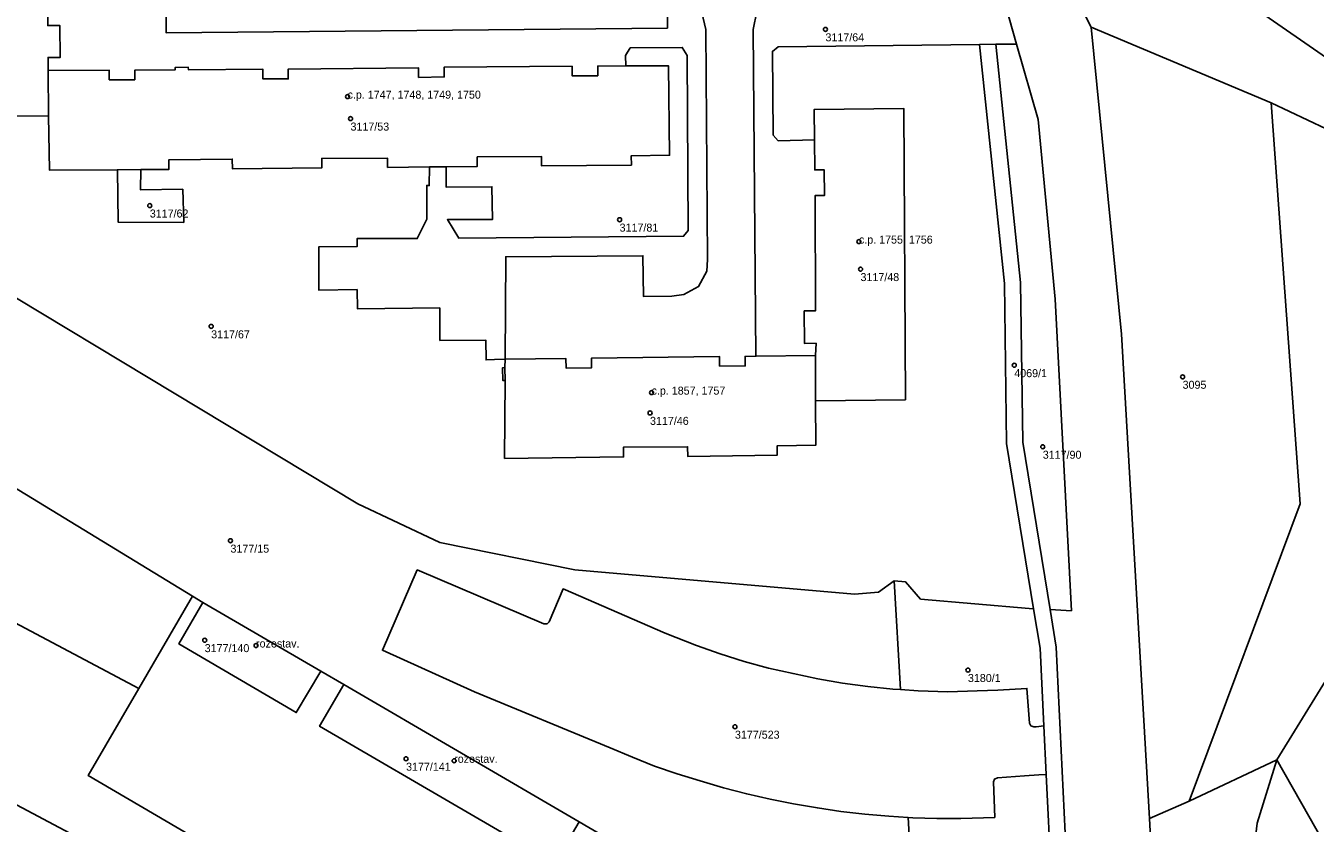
# Model space of a CAD drawing. Extents: x -878211 to -870363, y -1058464 to -1052522.
# Drawn here: x -874028.3 to -873867.2, y -1056949.6 to -1056850 of the extents above; entities that cross this region are included whole.
import ezdxf

# ---------------------------------------------------------------- set-up
doc = ezdxf.new("R2010")
doc.units = 0
for name, color, linetype in [('Vrstva 50', 7, 'Continuous'), ('Vrstva 51', 7, 'Continuous'), ('Vrstva 52', 7, 'Continuous')]:
    doc.layers.add(name, color=color, linetype=linetype)

msp = doc.modelspace()

# ---------------------------------------------------------------- linework, layer by layer
at = {"layer": 'Vrstva 50'}
for centre in [(-873928.43, -1056850.41994), (-873988.14, -1056858.81994), (-873987.77, -1056861.56994), (-874012.85, -1056872.42994), (-873954.15, -1056874.18994), (-873924.25, -1056876.92994), (-873924.05, -1056880.36994), (-874005.18, -1056887.51994), (-873904.84, -1056892.36994), (-873883.81, -1056893.81994), (-873950.16, -1056895.78994), (-873950.35, -1056898.32994), (-873901.28, -1056902.55994), (-874002.77, -1056914.28994), (-874005.99, -1056926.71994), (-873999.57, -1056927.37994), (-873910.63, -1056930.44994), (-873939.74, -1056937.52994), (-873980.83, -1056941.52994), (-873974.82, -1056941.77994)]:
    msp.add_circle(centre, 0.25, dxfattribs=at)
at = {"layer": 'Vrstva 51'}
for points in [[(-873604.63, -1056840.36), (-873616.81, -1056858.72), (-873698.72, -1056860.89), (-873766.2, -1056862.68), (-873840.53, -1056864.49), (-873842.61, -1056864.54), (-873904.62, -1056821.65), (-873906.75, -1056817.03), (-873920.07, -1056788.11), (-873936.35, -1056752.76), (-873946.72, -1056739.16), (-873949.55, -1056741.32), (-873950.29, -1056741.89), (-873940.24, -1056755.07), (-873908.21, -1056824.62), (-873843.96, -1056869.08), (-873693.74, -1056865.21), (-873616.51, -1056863.22), (-873608.69, -1056855.43), (-873599.24, -1056841.86)], [(-874049.34, -1056914.15), (-874014.23, -1056932.75), (-874007.51, -1056921.23), (-874042.84, -1056899.69), (-874076.67, -1056880.17), (-874135.18, -1056846.79), (-874225.05, -1056794.29), (-874220.11, -1056799.06), (-874203.06, -1056813.57), (-874129.69, -1056863.48), (-874108.33, -1056874.46), (-874102.53, -1056878.64), (-874078.93, -1056895.35), (-874073.45, -1056899.05), (-874056.93, -1056909.47)], [(-874038.33, -1056836.04), (-874036.85, -1056836.02), (-874036.75, -1056861.29), (-874025.49, -1056861.21), (-874025.55, -1056855.56), (-874025.56, -1056853.92), (-874024.03, -1056853.91), (-874024.08, -1056849.94), (-874025.59, -1056849.95), (-874025.75, -1056836.37), (-874025.88, -1056824.74), (-874037.05, -1056824.85), (-874036.93, -1056830.52), (-874036.91, -1056831.66), (-874036.9, -1056832), (-874038.38, -1056832.02), (-874038.34, -1056835.71)], [(-873872.76, -1056859.6), (-873856.69, -1056867.17), (-873849.21, -1056874.21), (-873847.06, -1056896.27), (-873844.64, -1056897.18), (-873805.03, -1056873.43), (-873843.96, -1056869.08), (-873908.21, -1056824.62), (-873895.24, -1056850.14)], [(-873891.46, -1056888.5), (-873887.93, -1056948.97), (-873882.99, -1056946.82), (-873869.1, -1056909.7), (-873872.76, -1056859.6), (-873895.24, -1056850.14)], [(-873975.82, -1056867.58), (-873975.8, -1056870.14), (-873970.1, -1056870.08), (-873970.01, -1056874.16), (-873975.66, -1056874.17), (-873974.22, -1056876.5), (-873946.15, -1056876.25), (-873945.59, -1056875.55), (-873945.69, -1056853.68), (-873946.33, -1056852.68), (-873952.81, -1056852.74), (-873953.42, -1056853.7), (-873953.37, -1056854.98), (-873948.06, -1056854.96), (-873947.91, -1056866.14), (-873952.69, -1056866.2), (-873952.67, -1056867.36), (-873963.9, -1056867.47), (-873963.92, -1056866.29), (-873971.94, -1056866.35), (-873971.93, -1056867.53)], [(-873900.85, -1056943.5), (-873900.25, -1056956.07), (-873898.25, -1056955.98), (-873899.61, -1056927.59), (-873900.37, -1056922.89), (-873903.77, -1056901.98), (-873904.06, -1056882.04), (-873907.15, -1056852.28), (-873909.17, -1056852.29), (-873906.07, -1056882.18), (-873905.81, -1056902.14), (-873902.42, -1056922.78), (-873901.61, -1056927.7), (-873901.14, -1056937.42)], [(-873903.77, -1056901.98), (-873900.37, -1056922.89), (-873897.7, -1056923.04), (-873899.71, -1056884.1), (-873901.85, -1056861.67), (-873904.55, -1056852.25), (-873907.15, -1056852.28), (-873904.06, -1056882.04)], [(-874025.55, -1056855.56), (-874025.49, -1056861.21), (-874025.37, -1056868.01), (-874016.89, -1056867.96), (-874013.95, -1056867.94), (-874010.46, -1056867.92), (-874010.47, -1056866.72), (-874002.54, -1056866.62), (-874002.53, -1056867.82), (-873991.36, -1056867.73), (-873991.37, -1056866.53), (-873983.16, -1056866.49), (-873983.14, -1056867.66), (-873977.91, -1056867.6), (-873975.82, -1056867.58), (-873971.93, -1056867.53), (-873971.94, -1056866.35), (-873963.92, -1056866.29), (-873963.9, -1056867.47), (-873952.67, -1056867.36), (-873952.69, -1056866.2), (-873947.91, -1056866.14), (-873948.06, -1056854.96), (-873953.37, -1056854.98), (-873956.88, -1056855), (-873956.88, -1056856.21), (-873960.09, -1056856.22), (-873960.09, -1056855.02), (-873976.08, -1056855.15), (-873976.05, -1056856.36), (-873979.27, -1056856.42), (-873979.29, -1056855.21), (-873995.54, -1056855.38), (-873995.55, -1056856.61), (-873998.74, -1056856.58), (-873998.73, -1056855.38), (-874008.03, -1056855.46), (-874008.05, -1056855.14), (-874009.67, -1056855.16), (-874009.66, -1056855.47), (-874014.73, -1056855.52), (-874014.73, -1056856.72), (-874017.91, -1056856.72), (-874017.92, -1056855.53)], [(-873856.69, -1056867.17), (-873872.76, -1056859.6), (-873869.1, -1056909.7), (-873882.99, -1056946.82), (-873872.02, -1056941.65), (-873844.64, -1056897.18), (-873847.06, -1056896.27), (-873849.21, -1056874.21)], [(-873929.84, -1056860.41), (-873929.8, -1056864.2), (-873929.76, -1056867.98), (-873928.58, -1056867.97), (-873928.55, -1056871.17), (-873929.73, -1056871.18), (-873929.66, -1056885.57), (-873931.08, -1056885.58), (-873931.05, -1056889.65), (-873929.61, -1056889.63), (-873929.67, -1056891.15), (-873929.68, -1056896.81), (-873918.43, -1056896.69), (-873918.65, -1056860.29)], [(-874129.69, -1056863.48), (-874140.36, -1056880.4), (-874060.01, -1056931.07), (-874021.49, -1056951.53), (-873984.94, -1056965.93), (-873981.56, -1056966.45), (-874020.56, -1056943.6), (-874014.23, -1056932.75), (-874049.34, -1056914.15), (-874056.93, -1056909.47), (-874073.45, -1056899.05), (-874078.93, -1056895.35), (-874102.53, -1056878.64), (-874108.33, -1056874.46)], [(-874013.95, -1056867.94), (-874016.89, -1056867.96), (-874016.8, -1056874.48), (-874008.61, -1056874.52), (-874008.73, -1056870.39), (-874014.02, -1056870.46)], [(-873844.64, -1056897.18), (-873872.02, -1056941.65), (-873797.84, -1057072.28), (-873673.86, -1057000.71), (-873709.07, -1056941.13), (-873712.1, -1056942.73), (-873755.06, -1056869.97), (-873805.03, -1056873.43)], [(-873960.84, -1056892.72), (-873960.86, -1056891.53), (-873968.46, -1056891.62), (-873968.47, -1056892.67), (-873968.76, -1056892.68), (-873968.73, -1056894.28), (-873968.45, -1056894.28), (-873968.51, -1056904), (-873953.66, -1056903.82), (-873953.67, -1056902.62), (-873945.66, -1056902.55), (-873945.64, -1056903.75), (-873934.45, -1056903.6), (-873934.46, -1056902.42), (-873929.65, -1056902.36), (-873929.68, -1056896.81), (-873929.67, -1056891.15), (-873937.11, -1056891.24), (-873938.48, -1056891.26), (-873938.46, -1056892.45), (-873941.65, -1056892.48), (-873941.66, -1056891.29), (-873957.68, -1056891.49), (-873957.66, -1056892.69)], [(-873907.3, -1056944.06), (-873906.95, -1056943.9), (-873903.58, -1056943.66), (-873901.78, -1056943.52), (-873900.85, -1056943.5), (-873901.14, -1056937.42), (-873902.12, -1056937.52), (-873902.4, -1056937.54), (-873902.76, -1056937.4), (-873902.93, -1056937.08), (-873903.26, -1056932.74), (-873906.89, -1056932.94), (-873909.49, -1056933.05), (-873913.13, -1056933.15), (-873916.86, -1056933.05), (-873919.05, -1056932.89), (-873920.02, -1056932.83), (-873923.14, -1056932.5), (-873926.3, -1056932.09), (-873929.38, -1056931.56), (-873932.47, -1056930.89), (-873935.56, -1056930.19), (-873938.57, -1056929.36), (-873941.58, -1056928.4), (-873944.56, -1056927.39), (-873948.45, -1056925.82), (-873961.21, -1056920.3), (-873962.95, -1056924.42), (-873963.19, -1056924.67), (-873963.6, -1056924.67), (-873979.44, -1056917.94), (-873983.79, -1056927.97), (-873972.27, -1056933.16), (-873955.34, -1056940.16), (-873952.55, -1056941.33), (-873949.77, -1056942.43), (-873946.94, -1056943.41), (-873944.08, -1056944.3), (-873941.18, -1056945.15), (-873938.26, -1056945.91), (-873935.35, -1056946.57), (-873932.41, -1056947.15), (-873929.44, -1056947.66), (-873926.49, -1056948.1), (-873923.51, -1056948.45), (-873920.51, -1056948.71), (-873918.11, -1056948.85), (-873917.52, -1056948.89), (-873914.5, -1056948.99), (-873911.5, -1056949), (-873907.28, -1056948.86), (-873907.42, -1056944.41)], [(-873903.26, -1056932.74), (-873902.93, -1056937.08), (-873902.76, -1056937.4), (-873902.4, -1056937.54), (-873902.12, -1056937.52), (-873901.14, -1056937.42), (-873901.61, -1056927.7), (-873902.42, -1056922.78), (-873902.99, -1056922.75), (-873916.54, -1056921.58), (-873918.41, -1056919.44), (-873919.86, -1056919.3), (-873919.05, -1056932.89), (-873916.86, -1056933.05), (-873913.13, -1056933.15), (-873909.49, -1056933.05), (-873906.89, -1056932.94)], [(-874006.21, -1056921.99), (-874009.2, -1056927.18), (-873994.54, -1056935.75), (-873991.46, -1056930.6)], [(-873988.6, -1056932.27), (-873991.63, -1056937.46), (-873972.19, -1056948.79), (-873962.24, -1056954.58), (-873959.22, -1056949.41)], [(-873856.51, -1057143.18), (-873856, -1057126.59), (-873855.59, -1057113.18), (-873859.53, -1057099.33), (-873861.95, -1057049.13), (-873875.62, -1056959.25), (-873874.5, -1056949.59), (-873872.02, -1056941.65), (-873882.99, -1056946.82), (-873887.93, -1056948.97), (-873887.66, -1056954.58), (-873884.35, -1057010.32), (-873881.61, -1057032.55)], [(-873918.11, -1056948.85), (-873917.62, -1056957.07), (-873910.53, -1056956.56), (-873900.25, -1056956.07), (-873900.85, -1056943.5), (-873901.78, -1056943.52), (-873903.58, -1056943.66), (-873906.95, -1056943.9), (-873907.3, -1056944.06), (-873907.42, -1056944.41), (-873907.28, -1056948.86), (-873911.5, -1056949), (-873914.5, -1056948.99), (-873917.52, -1056948.89)]]:
    msp.add_lwpolyline(points, close=True, dxfattribs=at)
for points in [[(-874156.66, -1056907.49), (-874136.75, -1056919.68), (-874118.33, -1056927.78), (-874098.29, -1056936.6), (-874078.24, -1056945.42), (-874058.2, -1056954.24), (-874038.15, -1056963.06), (-874037.51, -1056961.6), (-874024.26, -1056967.4), (-874010.99, -1056973.2), (-873996.88, -1056979.37), (-873982.81, -1056985.53), (-873969.85, -1056991.2), (-873968.72, -1056991.43), (-873957.55, -1056993.69), (-873942.44, -1056994.26), (-873933.49, -1056994.6), (-873981.56, -1056966.45), (-873984.94, -1056965.93), (-874021.49, -1056951.53), (-874060.01, -1056931.07), (-874140.36, -1056880.4), (-874129.69, -1056863.48), (-874203.06, -1056813.57)], [(-873856.51, -1057143.18), (-873881.61, -1057032.55), (-873884.35, -1057010.32), (-873887.66, -1056954.58), (-873887.93, -1056948.97), (-873891.46, -1056888.5), (-873895.24, -1056850.14), (-873908.21, -1056824.62)], [(-873948.19, -1056845.24), (-873948.18, -1056850.25), (-874010.8, -1056850.85), (-874010.84, -1056845.75)], [(-874010.84, -1056845.75), (-874010.8, -1056850.85), (-873948.18, -1056850.25), (-873948.19, -1056845.24)], [(-874024.08, -1056849.94), (-874024.03, -1056853.91), (-874025.56, -1056853.92), (-874025.55, -1056855.56), (-874017.92, -1056855.53), (-874017.91, -1056856.72), (-874014.73, -1056856.72), (-874014.73, -1056855.52), (-874009.66, -1056855.47), (-874009.67, -1056855.16), (-874008.05, -1056855.14), (-874008.03, -1056855.46), (-873998.73, -1056855.38), (-873998.74, -1056856.58), (-873995.55, -1056856.61), (-873995.54, -1056855.38), (-873979.29, -1056855.21), (-873979.27, -1056856.42), (-873976.05, -1056856.36), (-873976.08, -1056855.15), (-873960.09, -1056855.02), (-873960.09, -1056856.22), (-873956.88, -1056856.21), (-873956.88, -1056855), (-873953.37, -1056854.98), (-873953.42, -1056853.7), (-873952.81, -1056852.74), (-873946.33, -1056852.68), (-873945.69, -1056853.68), (-873945.59, -1056875.55), (-873946.15, -1056876.25), (-873974.22, -1056876.5), (-873975.66, -1056874.17), (-873970.01, -1056874.16), (-873970.1, -1056870.08), (-873975.8, -1056870.14), (-873975.82, -1056867.58), (-873977.91, -1056867.6), (-873977.93, -1056869.93), (-873978.24, -1056869.9), (-873978.22, -1056874.14), (-873979.44, -1056876.54), (-873986.92, -1056876.52), (-873986.92, -1056877.52), (-873991.72, -1056877.56), (-873991.71, -1056883.01), (-873986.94, -1056882.91), (-873986.9, -1056885.31), (-873976.62, -1056885.22), (-873976.6, -1056889.28), (-873970.85, -1056889.24), (-873970.84, -1056891.71), (-873969.76, -1056891.67), (-873968.46, -1056891.62), (-873968.38, -1056878.82), (-873951.24, -1056878.7), (-873951.18, -1056883.78), (-873947.61, -1056883.75), (-873946.11, -1056883.52), (-873944.29, -1056882.55), (-873943.26, -1056880.64), (-873943.18, -1056879.16), (-873943.39, -1056850.43), (-873943.87, -1056848.32)], [(-873943.87, -1056848.32), (-873943.39, -1056850.43), (-873943.18, -1056879.16), (-873943.26, -1056880.64), (-873944.29, -1056882.55), (-873946.11, -1056883.52), (-873947.61, -1056883.75), (-873951.18, -1056883.78), (-873951.24, -1056878.7), (-873968.38, -1056878.82), (-873968.46, -1056891.62), (-873960.86, -1056891.53), (-873960.84, -1056892.72), (-873957.66, -1056892.69), (-873957.68, -1056891.49), (-873941.66, -1056891.29), (-873941.65, -1056892.48), (-873938.46, -1056892.45), (-873938.48, -1056891.26), (-873937.11, -1056891.24), (-873937.46, -1056850.42), (-873936.99, -1056848.2)], [(-873936.99, -1056848.2), (-873937.46, -1056850.42), (-873937.11, -1056891.24), (-873929.67, -1056891.15), (-873929.61, -1056889.63), (-873931.05, -1056889.65), (-873931.08, -1056885.58), (-873929.66, -1056885.57), (-873929.73, -1056871.18), (-873928.55, -1056871.17), (-873928.58, -1056867.97), (-873929.76, -1056867.98), (-873929.8, -1056864.2), (-873934.32, -1056864.34), (-873934.95, -1056863.63), (-873935.06, -1056853.17), (-873934.33, -1056852.58), (-873909.17, -1056852.29), (-873907.15, -1056852.28), (-873904.55, -1056852.25), (-873905.95, -1056847.41)], [(-873905.95, -1056847.41), (-873904.55, -1056852.25), (-873901.85, -1056861.67), (-873899.71, -1056884.1), (-873897.7, -1056923.04), (-873900.37, -1056922.89), (-873899.61, -1056927.59), (-873898.25, -1056955.98), (-873898.03, -1056955.97), (-873897.18, -1056955.92), (-873896.36, -1056973.46), (-873895.72, -1056985.08), (-873893.67, -1057021.77), (-873892.27, -1057033.58), (-873889.52, -1057047.9), (-873887.76, -1057055.87), (-873882.49, -1057079.7), (-873873.31, -1057121.91), (-873867.32, -1057147.86)], [(-874032.81, -1056882.03), (-873986.86, -1056909.69), (-873976.6, -1056914.5), (-873959.75, -1056917.91), (-873924.82, -1056920.96), (-873921.8, -1056920.73), (-873919.86, -1056919.3), (-873918.41, -1056919.44), (-873916.54, -1056921.58), (-873902.99, -1056922.75), (-873902.42, -1056922.78), (-873905.81, -1056902.14), (-873906.07, -1056882.18), (-873909.17, -1056852.29), (-873934.33, -1056852.58), (-873935.06, -1056853.17), (-873934.95, -1056863.63), (-873934.32, -1056864.34), (-873929.8, -1056864.2), (-873929.84, -1056860.41), (-873918.65, -1056860.29), (-873918.43, -1056896.69), (-873929.68, -1056896.81), (-873929.65, -1056902.36), (-873934.46, -1056902.42), (-873934.45, -1056903.6), (-873945.64, -1056903.75), (-873945.66, -1056902.55), (-873953.67, -1056902.62), (-873953.66, -1056903.82), (-873968.51, -1056904), (-873968.45, -1056894.28), (-873968.73, -1056894.28), (-873968.76, -1056892.68), (-873968.47, -1056892.67), (-873968.46, -1056891.62), (-873969.76, -1056891.67), (-873970.84, -1056891.71), (-873970.85, -1056889.24), (-873976.6, -1056889.28), (-873976.62, -1056885.22), (-873986.9, -1056885.31), (-873986.94, -1056882.91), (-873991.71, -1056883.01), (-873991.72, -1056877.56), (-873986.92, -1056877.52), (-873986.92, -1056876.52), (-873979.44, -1056876.54), (-873978.22, -1056874.14), (-873978.24, -1056869.9), (-873977.93, -1056869.93), (-873977.91, -1056867.6), (-873983.14, -1056867.66), (-873983.16, -1056866.49), (-873991.37, -1056866.53), (-873991.36, -1056867.73), (-874002.53, -1056867.82), (-874002.54, -1056866.62), (-874010.47, -1056866.72), (-874010.46, -1056867.92), (-874013.95, -1056867.94), (-874014.02, -1056870.46), (-874008.73, -1056870.39), (-874008.61, -1056874.52), (-874016.8, -1056874.48), (-874016.89, -1056867.96), (-874025.37, -1056868.01), (-874025.49, -1056861.21), (-874036.75, -1056861.29)], [(-873917.62, -1056957.07), (-873918.11, -1056948.85), (-873920.51, -1056948.71), (-873923.51, -1056948.45), (-873926.49, -1056948.1), (-873929.44, -1056947.66), (-873932.41, -1056947.15), (-873935.35, -1056946.57), (-873938.26, -1056945.91), (-873941.18, -1056945.15), (-873944.08, -1056944.3), (-873946.94, -1056943.41), (-873949.77, -1056942.43), (-873952.55, -1056941.33), (-873955.34, -1056940.16), (-873972.27, -1056933.16), (-873983.79, -1056927.97), (-873979.44, -1056917.94), (-873963.6, -1056924.67), (-873963.19, -1056924.67), (-873962.95, -1056924.42), (-873961.21, -1056920.3), (-873948.45, -1056925.82), (-873944.56, -1056927.39), (-873941.58, -1056928.4), (-873938.57, -1056929.36), (-873935.56, -1056930.19), (-873932.47, -1056930.89), (-873929.38, -1056931.56), (-873926.3, -1056932.09), (-873923.14, -1056932.5), (-873920.02, -1056932.83), (-873919.05, -1056932.89), (-873919.86, -1056919.3), (-873921.8, -1056920.73), (-873924.82, -1056920.96), (-873959.75, -1056917.91), (-873976.6, -1056914.5), (-873986.86, -1056909.69), (-874032.81, -1056882.03)], [(-874042.84, -1056899.69), (-874007.51, -1056921.23), (-874006.21, -1056921.99), (-873991.46, -1056930.6), (-873988.6, -1056932.27), (-873959.22, -1056949.41), (-873956.29, -1056951.12)], [(-873571.9, -1057164.95), (-873603.64, -1057115.36), (-873646.95, -1057049.06), (-873663.43, -1057018.39), (-873649.57, -1057009.83), (-873687.72, -1056941.74), (-873643.87, -1056914.15), (-873662.81, -1056904.24), (-873704.72, -1056929.29), (-873709.07, -1056941.13), (-873673.86, -1057000.71), (-873797.84, -1057072.28), (-873872.02, -1056941.65), (-873874.5, -1056949.59), (-873875.62, -1056959.25), (-873861.95, -1057049.13), (-873859.53, -1057099.33), (-873855.59, -1057113.18), (-873856, -1057126.59), (-873787.09, -1057093.26), (-873671.57, -1057028.78), (-873658.46, -1057052.59), (-873628.55, -1057098.75), (-873585.02, -1057169.44)], [(-873956.29, -1056951.12), (-873959.22, -1056949.41), (-873962.24, -1056954.58), (-873972.19, -1056948.79), (-873991.63, -1056937.46), (-873988.6, -1056932.27), (-873991.46, -1056930.6), (-873994.54, -1056935.75), (-874009.2, -1056927.18), (-874006.21, -1056921.99), (-874007.51, -1056921.23), (-874014.23, -1056932.75), (-874020.56, -1056943.6), (-873981.56, -1056966.45)]]:
    msp.add_lwpolyline(points, dxfattribs=at)
at = {"layer": 'Vrstva 52'}
for points in [[(-874025.75, -1056836.37), (-874025.88, -1056824.74), (-874037.05, -1056824.85), (-874036.93, -1056830.52), (-874036.91, -1056831.66), (-874036.9, -1056832), (-874038.38, -1056832.02), (-874038.34, -1056835.71), (-874038.33, -1056836.04), (-874036.85, -1056836.02), (-874036.75, -1056861.29), (-874025.49, -1056861.21), (-874025.55, -1056855.56), (-874025.56, -1056853.92), (-874024.03, -1056853.91), (-874024.08, -1056849.94), (-874025.59, -1056849.95)], [(-874010.47, -1056866.72), (-874002.54, -1056866.62), (-874002.53, -1056867.82), (-873991.36, -1056867.73), (-873991.37, -1056866.53), (-873983.16, -1056866.49), (-873983.14, -1056867.66), (-873977.91, -1056867.6), (-873975.82, -1056867.58), (-873971.93, -1056867.53), (-873971.94, -1056866.35), (-873963.92, -1056866.29), (-873963.9, -1056867.47), (-873952.67, -1056867.36), (-873952.69, -1056866.2), (-873947.91, -1056866.14), (-873948.06, -1056854.96), (-873953.37, -1056854.98), (-873956.88, -1056855), (-873956.88, -1056856.21), (-873960.09, -1056856.22), (-873960.09, -1056855.02), (-873976.08, -1056855.15), (-873976.05, -1056856.36), (-873979.27, -1056856.42), (-873979.29, -1056855.21), (-873995.54, -1056855.38), (-873995.55, -1056856.61), (-873998.74, -1056856.58), (-873998.73, -1056855.38), (-874008.03, -1056855.46), (-874008.05, -1056855.14), (-874009.67, -1056855.16), (-874009.66, -1056855.47), (-874014.73, -1056855.52), (-874014.73, -1056856.72), (-874017.91, -1056856.72), (-874017.92, -1056855.53), (-874025.55, -1056855.56), (-874025.49, -1056861.21), (-874025.37, -1056868.01), (-874016.89, -1056867.96), (-874013.95, -1056867.94), (-874010.46, -1056867.92)], [(-873928.55, -1056871.17), (-873929.73, -1056871.18), (-873929.66, -1056885.57), (-873931.08, -1056885.58), (-873931.05, -1056889.65), (-873929.61, -1056889.63), (-873929.67, -1056891.15), (-873929.68, -1056896.81), (-873918.43, -1056896.69), (-873918.65, -1056860.29), (-873929.84, -1056860.41), (-873929.8, -1056864.2), (-873929.76, -1056867.98), (-873928.58, -1056867.97)], [(-873968.51, -1056904), (-873953.66, -1056903.82), (-873953.67, -1056902.62), (-873945.66, -1056902.55), (-873945.64, -1056903.75), (-873934.45, -1056903.6), (-873934.46, -1056902.42), (-873929.65, -1056902.36), (-873929.68, -1056896.81), (-873929.67, -1056891.15), (-873937.11, -1056891.24), (-873938.48, -1056891.26), (-873938.46, -1056892.45), (-873941.65, -1056892.48), (-873941.66, -1056891.29), (-873957.68, -1056891.49), (-873957.66, -1056892.69), (-873960.84, -1056892.72), (-873960.86, -1056891.53), (-873968.46, -1056891.62), (-873968.47, -1056892.67), (-873968.45, -1056894.28)], [(-874006.21, -1056921.99), (-874009.2, -1056927.18), (-873994.54, -1056935.75), (-873991.46, -1056930.6)], [(-873988.6, -1056932.27), (-873991.63, -1056937.46), (-873972.19, -1056948.79), (-873962.24, -1056954.58), (-873959.22, -1056949.41)]]:
    msp.add_lwpolyline(points, close=True, dxfattribs=at)

# ---------------------------------------------------------------- texts
at = {"layer": 'Vrstva 50'}
for s, p in [('3117/64', (-873928.43, -1056851.909)), ('c.p. 1747, 1748, 1749, 1750', (-873988.14, -1056859.07)), ('3117/53', (-873987.77, -1056863.059)), ('3117/62', (-874012.85, -1056873.919)), ('3117/81', (-873954.15, -1056875.679)), ('c.p. 1755, 1756', (-873924.25, -1056877.179)), ('3117/48', (-873924.05, -1056881.859)), ('3117/67', (-874005.18, -1056889.009)), ('4069/1', (-873904.84, -1056893.859)), ('c.p. 1857, 1757', (-873950.16, -1056896.04)), ('3095', (-873883.81, -1056895.309)), ('3117/46', (-873950.35, -1056899.819)), ('3117/90', (-873901.28, -1056904.049)), ('3177/15', (-874002.77, -1056915.779)), ('3177/140', (-874005.99, -1056928.209)), ('rozestav.', (-873999.57, -1056927.629)), ('3180/1', (-873910.63, -1056931.939)), ('3177/523', (-873939.74, -1056939.019)), ('3177/141', (-873980.83, -1056943.019)), ('rozestav.', (-873974.82, -1056942.03))]:
    msp.add_text(s, height=0.999996, dxfattribs=at).set_placement(p)

doc.saveas('drawing.dxf')
